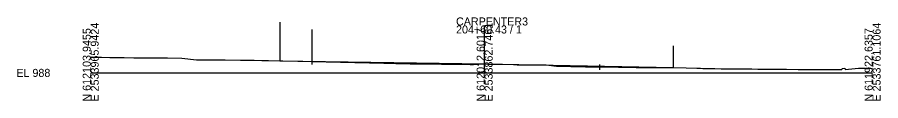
# Model space of a CAD drawing. Extents: x -120 to 2876, y -25 to 8560.
# Drawn here: x 2574.3 to 2876.4, y -9.7 to 19.4 of the extents above; entities that cross this region are included whole.
import ezdxf

# ---------------------------------------------------------------- set-up
doc = ezdxf.new("R2010")
doc.units = 0
for name, color, linetype in [('DESIGN - SCRATCH - User 2', 7, 'Continuous'), ('DESIGN - SHEET - Light Grid', 7, 'Continuous'), ('DESIGN - TYPICAL - Finished Grade and Subgrade', 7, 'Continuous'), ('SURVEY - GROUND - Top of Ground', 7, 'Continuous')]:
    doc.layers.add(name, color=color, linetype=linetype)

msp = doc.modelspace()

# ---------------------------------------------------------------- linework, layer by layer
at = {"layer": 'DESIGN - SCRATCH - User 2'}
for p, q in [((2666.29, 4.23), (2666.29, 17.74)), ((2803.74, 9.49), (2803.74, 1.83))]:
    msp.add_line(p, q, dxfattribs=at)
at = {"layer": 'DESIGN - SHEET - Light Grid'}
for p, q in [((2737.82, 0), (2737.82, 16.54)), ((2600, 0), (2737.82, 0)), ((2737.82, 0), (2873.55, 0))]:
    msp.add_line(p, q, dxfattribs=at)
at = {"layer": 'DESIGN - TYPICAL - Finished Grade and Subgrade'}
for p, q in [((2677.44, 2.91), (2677.44, 15.16)), ((2666.29, 4.23), (2737.82, 3.1)), ((2737.82, 3.1), (2803.74, 1.83)), ((2737.82, 3.1), (2799.83, 1.86)), ((2778.02, 2.91), (2778.02, 1.05))]:
    msp.add_line(p, q, dxfattribs=at)
at = {"layer": 'SURVEY - GROUND - Top of Ground'}
msp.add_lwpolyline([(2600, 5.44), (2601.59, 5.51), (2603.83, 5.49), (2606.65, 5.41), (2609.58, 5.39), (2611.7, 5.31), (2615.12, 5.29), (2616.75, 5.23), (2620.67, 5.22), (2621.8, 5.22), (2626.21, 5.21), (2626.86, 5.22), (2631.91, 5.19), (2636.99, 4.6), (2642.01, 4.56), (2644.48, 4.53), (2647.06, 4.51), (2652.38, 4.46), (2657.15, 4.38), (2659.9, 4.34), (2662.2, 4.3), (2666.12, 4.23), (2667.27, 4.2), (2672.47, 4.06), (2677.33, 3.93), (2677.72, 3.92), (2682.38, 3.82), (2682.93, 3.81), (2687.42, 3.71), (2688.03, 3.69), (2692.46, 3.59), (2693.13, 3.58), (2697.5, 3.48), (2698.23, 3.47), (2702.54, 3.37), (2706.75, 3.28), (2707.59, 3.26), (2711.74, 3.2), (2712.63, 3.18), (2713.51, 3.17), (2717.66, 3.12), (2718.61, 3.11), (2722.7, 3.07), (2723.7, 3.06), (2727.74, 3.04), (2728.79, 3.02), (2732.78, 2.92), (2733.89, 2.9), (2737.82, 3.1), (2738.98, 3.08), (2742.85, 3.07), (2744.07, 3.05), (2747.89, 2.87), (2749.16, 2.86), (2752.92, 2.83), (2754.24, 2.81), (2757.96, 2.78), (2759.33, 2.76), (2762.99, 2.4), (2764.41, 2.39), (2768.03, 2.23), (2769.52, 2.21), (2773.06, 2.08), (2784.65, 1.98), (2785.8, 1.97), (2790.88, 1.93), (2791.64, 1.92), (2792.41, 1.92), (2797.44, 1.88), (2797.82, 1.87), (2803.25, 1.83), (2803.94, 1.83), (2808.28, 1.71), (2812.01, 1.64), (2813.31, 1.6), (2814.15, 1.58), (2818.34, 1.5), (2820.51, 1.47), (2823.37, 1.44), (2825.97, 1.41), (2828.39, 1.39), (2831.35, 1.36), (2833.42, 1.34), (2836.74, 1.3), (2838.45, 1.29), (2842.12, 1.25), (2843.48, 1.24), (2847.5, 1.2), (2848.5, 1.19), (2852.88, 1.18), (2853.53, 1.17), (2858.56, 1.17), (2862.8, 1.16), (2862.95, 1.58), (2863.84, 1.64), (2863.91, 1.19), (2868.61, 1.65), (2871.01, 1.65), (2871.04, 1.4), (2873.55, 1.65)], dxfattribs=at)

# ---------------------------------------------------------------- texts
at = {"layer": 'DESIGN - SHEET - Light Grid'}
for s, p in [('CARPENTER3', (2727.82, 16.54)), ('204+60.43 / 1', (2727.82, 13.74)), ('EL 988', (2574, -1.4))]:
    msp.add_text(s, height=2.8, dxfattribs=at).set_placement(p)
for s, p in [('N 612103.9455', (2600, -10)), ('E 2533965.9424', (2602.8, -10)), ('N 612012.6017', (2737.82, -10)), ('E 2533862.7461', (2740.62, -10)), ('N 611922.6357', (2873.55, -10)), ('E 2533761.1064', (2876.35, -10))]:
    msp.add_text(s, height=2.8, rotation=90, dxfattribs=at).set_placement(p)

doc.saveas('drawing.dxf')
